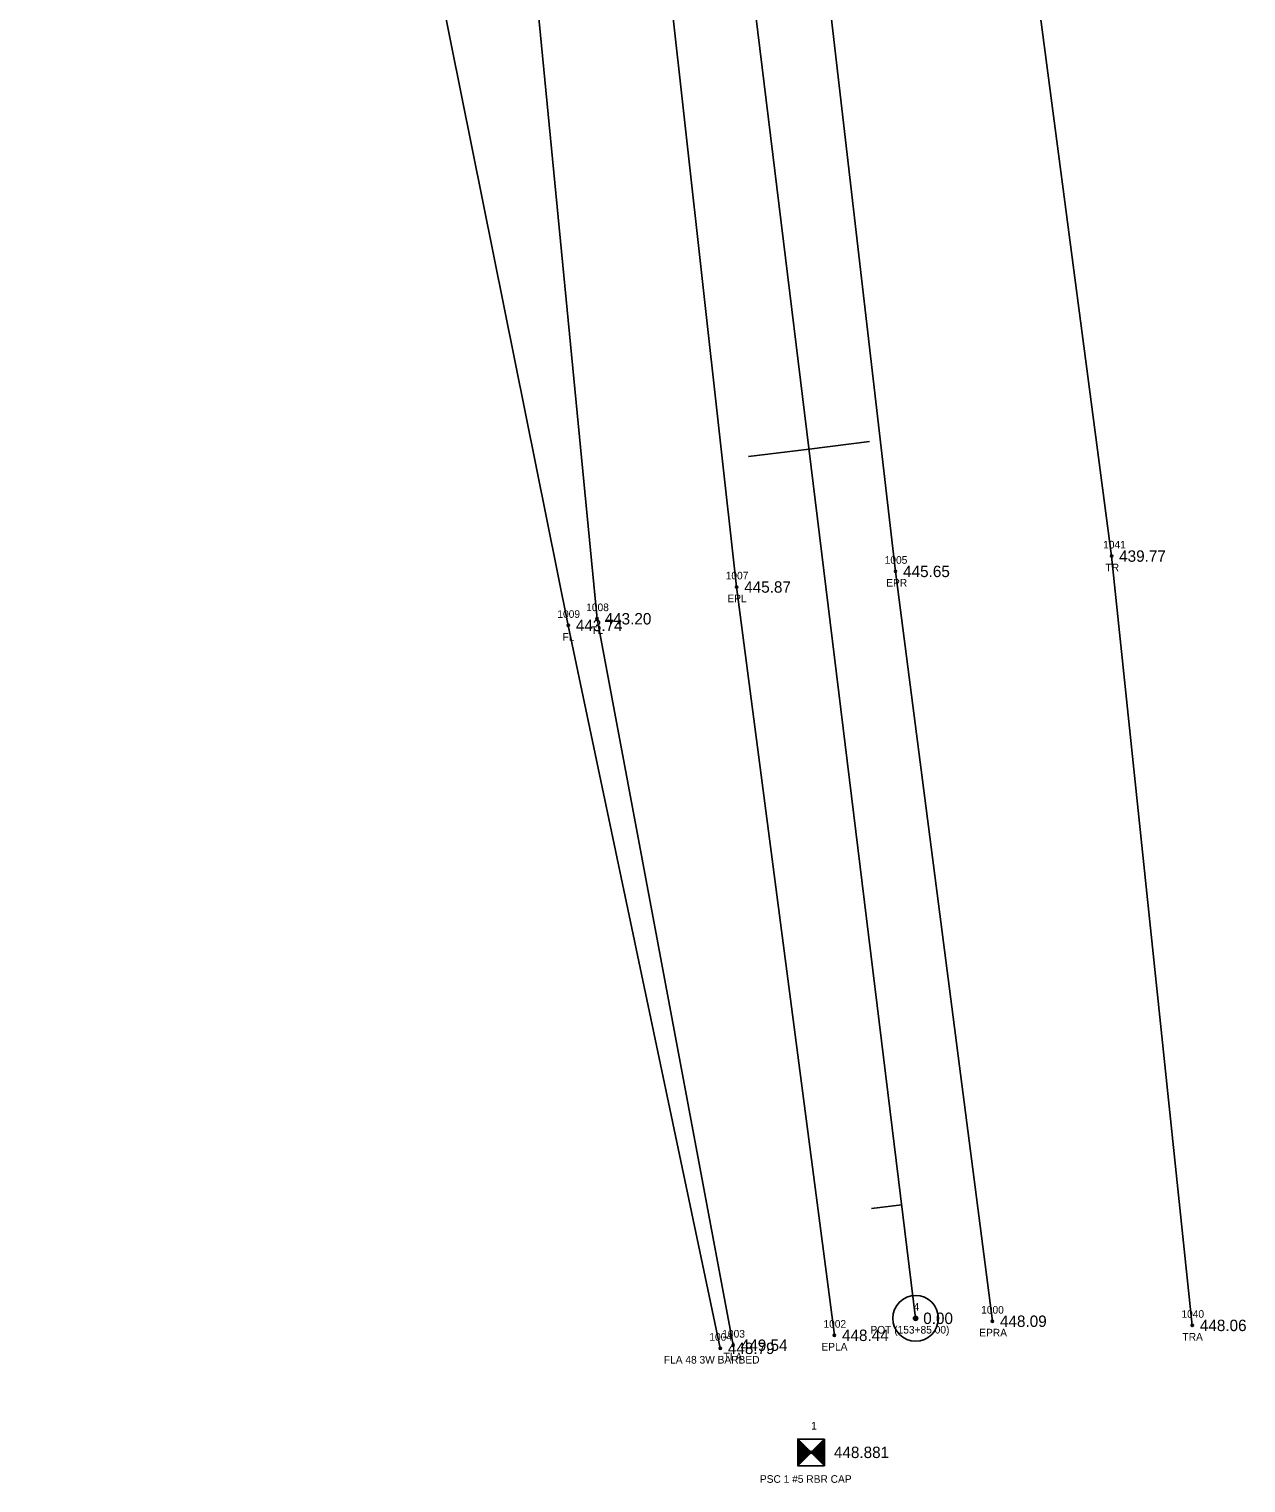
# Model space of a CAD drawing. Extents: x 1858454 to 1858924, y 1147053 to 1148170.
# Drawn here: x 1858633.8 to 1858793.6, y 1147052.9 to 1147243.8 of the extents above; entities that cross this region are included whole.
import ezdxf

# ---------------------------------------------------------------- set-up
doc = ezdxf.new("R2010")
doc.units = 0
for name, color, linetype in [('RD_EX_Fence_Other', 7, 'Continuous'), ('RD_EX_Fence_Other_txCode', 7, 'Continuous'), ('RD_EX_Road', 7, 'Continuous'), ('RD_EX_Road_txCode', 7, 'Continuous'), ('RD_EX_TX_Fence_Other_ELEV', 7, 'Continuous'), ('RD_EX_TX_Road_ELEV', 7, 'Continuous'), ('RD_EX_TX_VEG_ELEV', 7, 'Continuous'), ('RD_EX_VEG', 7, 'Continuous'), ('RD_EX_VEG_txCode', 7, 'Continuous'), ('RD_HC_Cl', 7, 'Continuous'), ('RD_HC_Data', 7, 'Continuous'), ('RD_HC_Data_Tic', 7, 'Continuous'), ('RD_HC_Survey', 7, 'Continuous'), ('RD_HC_Survey_ELEV', 7, 'Continuous'), ('RD_HC_txCode', 7, 'Continuous'), ('RD_SMD_Locator', 7, 'Continuous')]:
    doc.layers.add(name, color=color, linetype=linetype)

msp = doc.modelspace()

# ---------------------------------------------------------------- linework, layer by layer
at = {"layer": 'RD_EX_Fence_Other'}
msp.add_lwpolyline([(1858724.59, 1147070.61), (1858704.63, 1147165.53), (1858685.01, 1147263.02), (1858674.78, 1147319.72), (1858680.95, 1147360.94), (1858660.16, 1147468.71), (1858637.61, 1147560.56)], dxfattribs=at)
at = {"layer": 'RD_EX_Road'}
for points in [[(1858739.58, 1147072.32), (1858726.74, 1147170.58), (1858715.7, 1147269.68), (1858703.76, 1147368.69), (1858691.45, 1147468.11), (1858680.5, 1147569.65), (1858689.32, 1147570.79)], [(1858760.33, 1147074.17), (1858747.61, 1147172.63), (1858736.08, 1147271.97), (1858724.51, 1147372.2), (1858712.86, 1147470.38), (1858700.06, 1147571.96), (1858689.32, 1147570.79)]]:
    msp.add_lwpolyline(points, dxfattribs=at)
at = {"layer": 'RD_EX_VEG'}
for points in [[(1858786.58, 1147073.62), (1858775.98, 1147174.64), (1858762.89, 1147274.03), (1858752.24, 1147373.24), (1858736.96, 1147479.89), (1858729.06, 1147571.9), (1858711.6, 1147670.3), (1858690.41, 1147764.38), (1858680.89, 1147862.43), (1858668.42, 1147961.01), (1858651.26, 1148061.01), (1858641.53, 1148160.37)], [(1858726.29, 1147071.02), (1858708.41, 1147166.41), (1858698.92, 1147264.27), (1858694.52, 1147368.74), (1858682.22, 1147467.57), (1858636.43, 1147636.58), (1858645.41, 1147757.54), (1858631.11, 1147856.08), (1858618.46, 1147956.68), (1858606.82, 1148055.62), (1858592.91, 1148154.69)]]:
    msp.add_lwpolyline(points, dxfattribs=at)
at = {"layer": 'RD_HC_Cl'}
msp.add_line((1858750.25, 1147074.55), (1858617.68, 1148156.23), dxfattribs=at)
at = {"layer": 'RD_HC_Data'}
for radius in [3, 0.282]:
    msp.add_circle((1858750.25, 1147074.55), radius, dxfattribs=at)
at = {"layer": 'RD_HC_Data_Tic'}
for p, q in [((1858736.26, 1147188.7), (1858744.2, 1147189.67)), ((1858736.26, 1147188.7), (1858728.32, 1147187.73)), ((1858748.43, 1147089.44), (1858744.46, 1147088.95))]:
    msp.add_line(p, q, dxfattribs=at)
at = {"layer": 'RD_HC_Survey'}
for p, q in [((1858734.77, 1147058.7), (1858738.27, 1147055.2)), ((1858738.27, 1147058.7), (1858734.77, 1147055.2)), ((1858734.8, 1147058.68), (1858734.8, 1147055.23)), ((1858734.82, 1147058.65), (1858734.82, 1147055.25)), ((1858734.85, 1147058.63), (1858734.85, 1147055.27)), ((1858734.87, 1147058.6), (1858734.87, 1147055.3)), ((1858734.9, 1147058.58), (1858734.9, 1147055.32)), ((1858734.92, 1147058.55), (1858734.92, 1147055.35)), ((1858734.95, 1147058.53), (1858734.95, 1147055.37)), ((1858734.97, 1147058.5), (1858734.97, 1147055.4)), ((1858735, 1147058.48), (1858735, 1147055.42)), ((1858735.02, 1147058.45), (1858735.02, 1147055.45)), ((1858735.05, 1147058.43), (1858735.05, 1147055.47)), ((1858735.07, 1147058.4), (1858735.07, 1147055.5)), ((1858735.1, 1147058.38), (1858735.1, 1147055.52)), ((1858735.12, 1147058.35), (1858735.12, 1147055.55)), ((1858735.15, 1147058.33), (1858735.15, 1147055.57)), ((1858735.17, 1147058.3), (1858735.17, 1147055.6)), ((1858735.2, 1147058.28), (1858735.2, 1147055.62)), ((1858735.22, 1147058.25), (1858735.22, 1147055.65)), ((1858735.24, 1147058.23), (1858735.24, 1147055.67)), ((1858735.27, 1147058.21), (1858735.27, 1147055.7)), ((1858735.29, 1147058.18), (1858735.29, 1147055.72)), ((1858735.32, 1147058.16), (1858735.32, 1147055.74)), ((1858735.34, 1147058.13), (1858735.34, 1147055.77)), ((1858735.37, 1147058.11), (1858735.37, 1147055.79)), ((1858735.39, 1147058.08), (1858735.39, 1147055.82)), ((1858735.42, 1147058.06), (1858735.42, 1147055.84)), ((1858735.44, 1147058.03), (1858735.44, 1147055.87)), ((1858735.47, 1147058.01), (1858735.47, 1147055.89)), ((1858735.49, 1147057.98), (1858735.49, 1147055.92)), ((1858735.52, 1147057.96), (1858735.52, 1147055.94)), ((1858735.54, 1147057.93), (1858735.54, 1147055.97)), ((1858735.57, 1147057.91), (1858735.57, 1147055.99)), ((1858735.59, 1147057.88), (1858735.59, 1147056.02)), ((1858735.62, 1147057.86), (1858735.62, 1147056.04)), ((1858735.64, 1147057.83), (1858735.64, 1147056.07)), ((1858735.67, 1147057.81), (1858735.67, 1147056.09)), ((1858735.69, 1147057.78), (1858735.69, 1147056.12)), ((1858735.71, 1147057.76), (1858735.71, 1147056.14)), ((1858735.74, 1147057.74), (1858735.74, 1147056.17)), ((1858735.76, 1147057.71), (1858735.76, 1147056.19)), ((1858735.79, 1147057.69), (1858735.79, 1147056.22)), ((1858735.81, 1147057.66), (1858735.81, 1147056.24)), ((1858735.84, 1147057.64), (1858735.84, 1147056.26)), ((1858735.86, 1147057.61), (1858735.86, 1147056.29)), ((1858735.89, 1147057.59), (1858735.89, 1147056.31)), ((1858735.91, 1147057.56), (1858735.91, 1147056.34)), ((1858735.94, 1147057.54), (1858735.94, 1147056.36)), ((1858735.96, 1147057.51), (1858735.96, 1147056.39)), ((1858735.99, 1147057.49), (1858735.99, 1147056.41)), ((1858736.01, 1147057.46), (1858736.01, 1147056.44)), ((1858736.04, 1147057.44), (1858736.04, 1147056.46)), ((1858736.06, 1147057.41), (1858736.06, 1147056.49)), ((1858736.09, 1147057.39), (1858736.09, 1147056.51)), ((1858736.11, 1147057.36), (1858736.11, 1147056.54)), ((1858736.14, 1147057.34), (1858736.14, 1147056.56)), ((1858736.16, 1147057.31), (1858736.16, 1147056.59)), ((1858736.18, 1147057.29), (1858736.18, 1147056.61)), ((1858736.21, 1147057.26), (1858736.21, 1147056.64)), ((1858736.23, 1147057.24), (1858736.23, 1147056.66)), ((1858736.26, 1147057.22), (1858736.26, 1147056.69)), ((1858736.28, 1147057.19), (1858736.28, 1147056.71)), ((1858736.31, 1147057.17), (1858736.31, 1147056.73)), ((1858736.33, 1147057.14), (1858736.33, 1147056.76)), ((1858736.36, 1147057.12), (1858736.36, 1147056.78)), ((1858736.38, 1147057.09), (1858736.38, 1147056.81)), ((1858736.41, 1147057.07), (1858736.41, 1147056.83)), ((1858736.43, 1147057.04), (1858736.43, 1147056.86)), ((1858736.46, 1147057.02), (1858736.46, 1147056.88)), ((1858736.59, 1147057.02), (1858736.59, 1147056.88)), ((1858736.62, 1147057.04), (1858736.62, 1147056.86)), ((1858736.64, 1147057.07), (1858736.64, 1147056.83)), ((1858736.67, 1147057.09), (1858736.67, 1147056.81)), ((1858736.69, 1147057.12), (1858736.69, 1147056.78)), ((1858736.72, 1147057.14), (1858736.72, 1147056.76)), ((1858736.74, 1147057.17), (1858736.74, 1147056.73)), ((1858736.76, 1147057.19), (1858736.76, 1147056.71)), ((1858736.79, 1147057.22), (1858736.79, 1147056.69)), ((1858736.81, 1147057.24), (1858736.81, 1147056.66)), ((1858736.84, 1147057.26), (1858736.84, 1147056.64)), ((1858736.86, 1147057.29), (1858736.86, 1147056.61)), ((1858736.89, 1147057.31), (1858736.89, 1147056.59)), ((1858736.91, 1147057.34), (1858736.91, 1147056.56)), ((1858736.94, 1147057.36), (1858736.94, 1147056.54)), ((1858736.96, 1147057.39), (1858736.96, 1147056.51)), ((1858736.99, 1147057.41), (1858736.99, 1147056.49)), ((1858737.01, 1147057.44), (1858737.01, 1147056.46)), ((1858737.04, 1147057.46), (1858737.04, 1147056.44)), ((1858737.06, 1147057.49), (1858737.06, 1147056.41)), ((1858737.09, 1147057.51), (1858737.09, 1147056.39)), ((1858737.11, 1147057.54), (1858737.11, 1147056.36)), ((1858737.14, 1147057.56), (1858737.14, 1147056.34)), ((1858737.16, 1147057.59), (1858737.16, 1147056.31)), ((1858737.19, 1147057.61), (1858737.19, 1147056.29)), ((1858737.21, 1147057.64), (1858737.21, 1147056.26)), ((1858737.23, 1147057.66), (1858737.23, 1147056.24)), ((1858737.26, 1147057.69), (1858737.26, 1147056.22)), ((1858737.28, 1147057.71), (1858737.28, 1147056.19)), ((1858737.31, 1147057.74), (1858737.31, 1147056.17)), ((1858737.33, 1147057.76), (1858737.33, 1147056.14)), ((1858737.36, 1147057.78), (1858737.36, 1147056.12)), ((1858737.38, 1147057.81), (1858737.38, 1147056.09)), ((1858737.41, 1147057.83), (1858737.41, 1147056.07)), ((1858737.43, 1147057.86), (1858737.43, 1147056.04)), ((1858737.46, 1147057.88), (1858737.46, 1147056.02)), ((1858737.48, 1147057.91), (1858737.48, 1147055.99)), ((1858737.51, 1147057.93), (1858737.51, 1147055.97)), ((1858737.53, 1147057.96), (1858737.53, 1147055.94)), ((1858737.56, 1147057.98), (1858737.56, 1147055.92)), ((1858737.58, 1147058.01), (1858737.58, 1147055.89)), ((1858737.61, 1147058.03), (1858737.61, 1147055.87)), ((1858737.63, 1147058.06), (1858737.63, 1147055.84)), ((1858737.66, 1147058.08), (1858737.66, 1147055.82)), ((1858737.68, 1147058.11), (1858737.68, 1147055.79)), ((1858737.71, 1147058.13), (1858737.71, 1147055.77)), ((1858737.73, 1147058.16), (1858737.73, 1147055.74)), ((1858737.75, 1147058.18), (1858737.75, 1147055.72)), ((1858737.78, 1147058.21), (1858737.78, 1147055.7)), ((1858737.8, 1147058.23), (1858737.8, 1147055.67)), ((1858737.83, 1147058.25), (1858737.83, 1147055.65)), ((1858737.85, 1147058.28), (1858737.85, 1147055.62)), ((1858737.88, 1147058.3), (1858737.88, 1147055.6)), ((1858737.9, 1147058.33), (1858737.9, 1147055.57)), ((1858737.93, 1147058.35), (1858737.93, 1147055.55)), ((1858737.95, 1147058.38), (1858737.95, 1147055.52)), ((1858737.98, 1147058.4), (1858737.98, 1147055.5)), ((1858738, 1147058.43), (1858738, 1147055.47)), ((1858738.03, 1147058.45), (1858738.03, 1147055.45)), ((1858738.05, 1147058.48), (1858738.05, 1147055.42)), ((1858738.08, 1147058.5), (1858738.08, 1147055.4)), ((1858738.1, 1147058.53), (1858738.1, 1147055.37)), ((1858738.13, 1147058.55), (1858738.13, 1147055.35)), ((1858738.15, 1147058.58), (1858738.15, 1147055.32)), ((1858738.18, 1147058.6), (1858738.18, 1147055.3)), ((1858738.2, 1147058.63), (1858738.2, 1147055.27)), ((1858738.22, 1147058.65), (1858738.22, 1147055.25)), ((1858738.25, 1147058.68), (1858738.25, 1147055.23)), ((1858736.48, 1147056.99), (1858736.48, 1147056.91)), ((1858736.51, 1147056.97), (1858736.51, 1147056.93)), ((1858736.54, 1147056.97), (1858736.54, 1147056.93)), ((1858736.57, 1147056.99), (1858736.57, 1147056.91))]:
    msp.add_line(p, q, dxfattribs=at)
msp.add_lwpolyline([(1858738.27, 1147058.7), (1858734.77, 1147058.7), (1858734.77, 1147055.2), (1858738.27, 1147055.2)], close=True, dxfattribs=at)
at = {"layer": 'RD_SMD_Locator'}
for centre in [(1858775.98, 1147174.64), (1858747.61, 1147172.63), (1858726.74, 1147170.58), (1858708.41, 1147166.41), (1858704.63, 1147165.53), (1858750.25, 1147074.55), (1858760.33, 1147074.17), (1858739.58, 1147072.32), (1858786.58, 1147073.62), (1858724.59, 1147070.61), (1858726.29, 1147071.02), (1858736.52, 1147056.95)]:
    msp.add_circle(centre, 0.15, dxfattribs=at)

# ---------------------------------------------------------------- texts
at = {"layer": 'RD_EX_Fence_Other_txCode'}
for s, p in [('1009', (1858703.2, 1147166.53)), ('FL', (1858703.89, 1147163.53)), ('1004', (1858723.16, 1147071.61)), ('FLA 48 3W BARBED', (1858717.19, 1147068.61))]:
    msp.add_text(s, height=1, dxfattribs=at).set_placement(p)
at = {"layer": 'RD_EX_Road_txCode'}
for s, p in [('1005', (1858746.19, 1147173.63)), ('1007', (1858725.31, 1147171.58)), ('EPR', (1858746.39, 1147170.63)), ('EPL', (1858725.53, 1147168.58)), ('1000', (1858758.86, 1147075.17)), ('1002', (1858738.15, 1147073.32)), ('EPRA', (1858758.61, 1147072.17)), ('EPLA', (1858737.88, 1147070.32))]:
    msp.add_text(s, height=1, dxfattribs=at).set_placement(p)
at = {"layer": 'RD_EX_TX_Fence_Other_ELEV'}
for s, p in [('443.74', (1858705.63, 1147164.78)), ('448.79', (1858725.59, 1147069.86))]:
    msp.add_text(s, height=1.5, dxfattribs=at).set_placement(p)
at = {"layer": 'RD_EX_TX_Road_ELEV'}
for s, p in [('445.65', (1858748.61, 1147171.88)), ('445.87', (1858727.74, 1147169.83)), ('448.09', (1858761.33, 1147073.42)), ('448.44', (1858740.58, 1147071.57))]:
    msp.add_text(s, height=1.5, dxfattribs=at).set_placement(p)
at = {"layer": 'RD_EX_TX_VEG_ELEV'}
for s, p in [('439.77', (1858776.98, 1147173.89)), ('443.20', (1858709.41, 1147165.66)), ('448.06', (1858787.58, 1147072.87)), ('449.54', (1858727.29, 1147070.27))]:
    msp.add_text(s, height=1.5, dxfattribs=at).set_placement(p)
at = {"layer": 'RD_EX_VEG_txCode'}
for s, p in [('1041', (1858774.88, 1147175.64)), ('TR', (1858775.19, 1147172.64)), ('1008', (1858706.99, 1147167.41)), ('TL', (1858707.64, 1147164.41)), ('1040', (1858785.16, 1147074.62)), ('1003', (1858724.86, 1147072.02)), ('TRA', (1858785.3, 1147071.62)), ('TLA', (1858725.03, 1147069.02))]:
    msp.add_text(s, height=1, dxfattribs=at).set_placement(p)
at = {"layer": 'RD_HC_Survey_ELEV'}
for s, p in [('0.00', (1858751.25, 1147073.8)), ('448.881', (1858739.52, 1147056.2))]:
    msp.add_text(s, height=1.5, dxfattribs=at).set_placement(p)
at = {"layer": 'RD_HC_txCode'}
for s, p in [('4', (1858749.97, 1147075.55)), ('POT (153+85.00)', (1858744.32, 1147072.55)), ('1', (1858736.52, 1147059.95)), ('PSC 1 #5 RBR CAP', (1858729.8, 1147052.95))]:
    msp.add_text(s, height=1, dxfattribs=at).set_placement(p)

doc.saveas('drawing.dxf')
